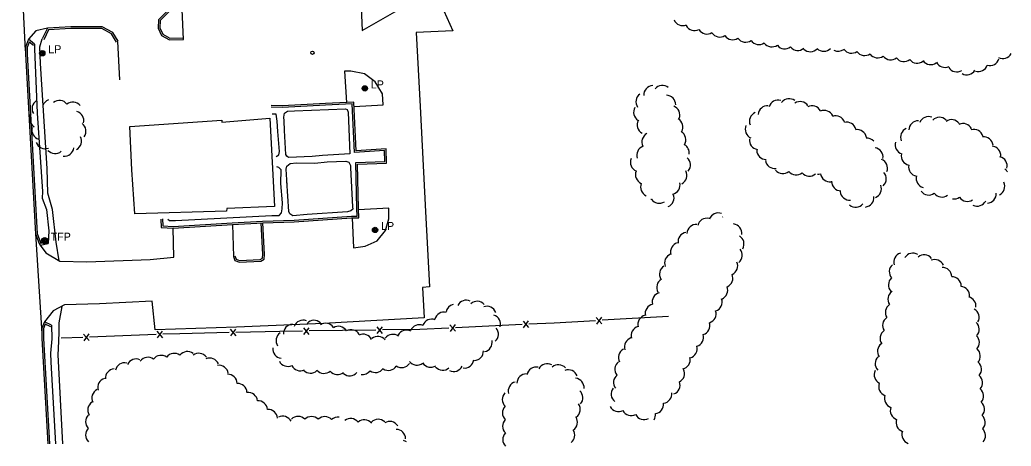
# Model space of a CAD drawing. Extents: x 2402803 to 2427059, y 6985292 to 6997652.
# Drawn here: x 2404119 to 2404714, y 6990684 to 6990940 of the extents above; entities that cross this region are included whole.
import ezdxf

# ---------------------------------------------------------------- set-up
doc = ezdxf.new("R2010")
doc.units = 0
for name, color, linetype in [('p_dtm sidewalk', 7, 'Continuous'), ('p_road - paved curb', 7, 'Continuous'), ('p_structure building', 7, 'Continuous'), ('p_structure fence', 7, 'Continuous'), ('p_structure general', 7, 'Continuous'), ('p_utility manhole', 7, 'Continuous'), ('p_veg woods', 7, 'Continuous')]:
    doc.layers.add(name, color=color, linetype=linetype)

msp = doc.modelspace()

# ---------------------------------------------------------------- linework, layer by layer
at = {"layer": 'p_dtm sidewalk'}
for points in [[(2404142.91, 6990795.04), (2404141.03, 6990806.28), (2404138.82, 6990825.86), (2404136.03, 6990835.62), (2404135.62, 6990850.54), (2404131.7, 6990913.61), (2404131.17, 6990923.49), (2404132.67, 6990928.22)], [(2404128.11, 6990925.14), (2404127.95, 6990922.36), (2404129.66, 6990883.71), (2404132.81, 6990836.75), (2404132.69, 6990832.8), (2404135.24, 6990825.97), (2404136.61, 6990813.18), (2404136.15, 6990805.59)], [(2404277.88, 6990873.33), (2404277.7, 6990879.05), (2404277.52, 6990881.37), (2404278.03, 6990883.76), (2404279.72, 6990884.93), (2404283.95, 6990885.13)], [(2404283.95, 6990885.13), (2404314.46, 6990886.32), (2404315.49, 6990885.96), (2404316.05, 6990884.39), (2404317.1, 6990859.35), (2404300.71, 6990858.22), (2404294.56, 6990857.64), (2404280.35, 6990857.21), (2404279.37, 6990857.89), (2404278.76, 6990859.01), (2404277.88, 6990873.33)], [(2404272.99, 6990857.7), (2404274.63, 6990858.69), (2404274.96, 6990860.63), (2404274.04, 6990872.64), (2404273.57, 6990878.94), (2404273.04, 6990883.09), (2404270.49, 6990883.07)], [(2404279.59, 6990840.44), (2404278.86, 6990850.21), (2404279.42, 6990852), (2404281.33, 6990853.46), (2404285.16, 6990853.89), (2404296.07, 6990853.79), (2404303.47, 6990854.51), (2404314.74, 6990854.84), (2404316.48, 6990854.36), (2404317.58, 6990852.31), (2404317.43, 6990851)], [(2404207.99, 6990820.1), (2404209.04, 6990819.22), (2404212.67, 6990819.25), (2404270.33, 6990822.38), (2404274.78, 6990822.31), (2404276.23, 6990823.96), (2404276.5, 6990826.3), (2404276.71, 6990830), (2404275.83, 6990841.48), (2404275.89, 6990849.63), (2404274.56, 6990851.17), (2404273.4, 6990851.53)], [(2404317.43, 6990851), (2404318.81, 6990827.54), (2404318.87, 6990826.2), (2404317.78, 6990825.14), (2404315.81, 6990824.52), (2404291.64, 6990823.01), (2404282.87, 6990822.17), (2404281.13, 6990823.39), (2404280.59, 6990824.78), (2404279.38, 6990843.21)], [(2404144.42, 6990767.8), (2404142.63, 6990758.01), (2404142.73, 6990751.91), (2404142.18, 6990742.61), (2404141.95, 6990738.66), (2404144.75, 6990685.25)], [(2404138.23, 6990756.48), (2404138.47, 6990748.33), (2404137.68, 6990739.81), (2404137.88, 6990734.32), (2404140.71, 6990685.27)]]:
    msp.add_lwpolyline(points, dxfattribs=at)
at = {"layer": 'p_road - paved curb'}
for points in [[(2404293.41, 6991178.81), (2404288.56, 6991177.04), (2404284.5, 6991172.88), (2404282.54, 6991167.82), (2404284.43, 6991126.82), (2404286.87, 6991077.05), (2404288.44, 6991043.11), (2404288.76, 6991035.23), (2404289.73, 6991010.43), (2404290.42, 6990974.99), (2404289.84, 6990969.34), (2404287.28, 6990963.88), (2404282.1, 6990961), (2404275.36, 6990959.94), (2404251.08, 6990959.64), (2404224.29, 6990958.49), (2404221.09, 6990957.34), (2404218.27, 6990955.63), (2404202.4, 6990939.81), (2404202.23, 6990934.79), (2404204.18, 6990930.34), (2404208.96, 6990927.68), (2404217.39, 6990928.01)], [(2404293.75, 6991177.87), (2404289.12, 6991176.18), (2404285.36, 6991172.33), (2404283.55, 6991167.66), (2404285.43, 6991126.87), (2404287.87, 6991077.1), (2404289.44, 6991043.15), (2404289.76, 6991035.27), (2404290.73, 6991010.46), (2404291.42, 6990974.95), (2404290.82, 6990969.07), (2404288.05, 6990963.16), (2404282.43, 6990960.04), (2404275.44, 6990958.94), (2404251.11, 6990958.64), (2404224.48, 6990957.5), (2404221.52, 6990956.43), (2404218.89, 6990954.84), (2404203.39, 6990939.38), (2404203.24, 6990934.98), (2404204.96, 6990931.05), (2404209.2, 6990928.69), (2404217.35, 6990929.01)], [(2404122.66, 6990921.17), (2404121.06, 6990953.84), (2404119.24, 6990983.48)], [(2404217.39, 6990928.01), (2404216.64, 6990945.87), (2404257.12, 6990947.89), (2404307.04, 6990950.75), (2404323.67, 6990951.86), (2404324.45, 6990933.39), (2404353.98, 6990950.06), (2404368, 6990957.22), (2404378.85, 6990933.11), (2404356.99, 6990932.15), (2404359.23, 6990887.62), (2404362.51, 6990824.66), (2404364.88, 6990779.51), (2404360.76, 6990779.03), (2404361.72, 6990760.99), (2404301.26, 6990757.57), (2404249.25, 6990755.35), (2404200.45, 6990753.66), (2404198.67, 6990771.01), (2404167.1, 6990769.36), (2404146.09, 6990768.63)], [(2404135.87, 6990934.69), (2404128.81, 6990933.05), (2404124.42, 6990928.05)], [(2404178.14, 6990926.88), (2404174.97, 6990932.16), (2404168.57, 6990935.61), (2404149.79, 6990935.56), (2404135.87, 6990934.69), (2404132.67, 6990928.22)], [(2404177.28, 6990926.37), (2404174.25, 6990931.41), (2404168.32, 6990934.61), (2404149.82, 6990934.56), (2404136.51, 6990933.73), (2404133.57, 6990927.78)], [(2404128.11, 6990925.14), (2404124.42, 6990928.05), (2404122.68, 6990923.24), (2404122.64, 6990919.1), (2404128.64, 6990811.29), (2404130.81, 6990805.6), (2404131.45, 6990804.58), (2404136.15, 6990805.59)], [(2404127.49, 6990924.35), (2404124.89, 6990926.41), (2404123.68, 6990923.06), (2404123.64, 6990919.12), (2404129.63, 6990811.5), (2404131.71, 6990806.05), (2404131.92, 6990805.7), (2404135.94, 6990806.57)], [(2404179.29, 6990903.78), (2404178.09, 6990926.77)], [(2404319.7, 6990887.68), (2404337.09, 6990888.79), (2404336.66, 6990895.31), (2404332.31, 6990902.48), (2404325.83, 6990907.24), (2404317.64, 6990908.83), (2404313.98, 6990908.82), (2404315.08, 6990890.16)], [(2404203.76, 6990820.19), (2404204.07, 6990815.06), (2404211.25, 6990814.78), (2404246.69, 6990816.96), (2404264.86, 6990817.97), (2404283.82, 6990818.55), (2404318.16, 6990820.88), (2404322.56, 6990820.99), (2404322.33, 6990826.31), (2404321.69, 6990853.07), (2404339.08, 6990853.79), (2404338.85, 6990862.38), (2404320.84, 6990861.18), (2404319.58, 6990890.38), (2404302.48, 6990889.55), (2404276.67, 6990888.03), (2404269.93, 6990888.34)], [(2404204.76, 6990820.25), (2404205.01, 6990816.02), (2404211.24, 6990815.78), (2404246.63, 6990817.96), (2404264.82, 6990818.97), (2404283.77, 6990819.55), (2404318.11, 6990821.88), (2404321.52, 6990821.96), (2404321.33, 6990826.28), (2404320.67, 6990854.03), (2404338.05, 6990854.75), (2404337.88, 6990861.31), (2404319.89, 6990860.11), (2404318.62, 6990889.33), (2404302.53, 6990888.55), (2404276.68, 6990887.03), (2404269.88, 6990887.34)], [(2404318.57, 6990820.89), (2404319.41, 6990802.82), (2404326.34, 6990803.82), (2404333.6, 6990807.05), (2404338.52, 6990813.24), (2404340.59, 6990820.36), (2404340.45, 6990826.77), (2404322.35, 6990825.76)], [(2404131.45, 6990804.58), (2404134.81, 6990799.95), (2404143.21, 6990794.86), (2404159.5, 6990794.58), (2404197.44, 6990795.94), (2404211.65, 6990797.34), (2404211.25, 6990814.78)], [(2404246.69, 6990816.96), (2404247.32, 6990797.71)], [(2404247.32, 6990797.71), (2404248.26, 6990795.26), (2404250.89, 6990794.26), (2404263.66, 6990794.86), (2404265.77, 6990796.11), (2404265.88, 6990798.94), (2404264.86, 6990817.97)], [(2404248.25, 6990798.07), (2404249.03, 6990796.04), (2404251.05, 6990795.27), (2404263.36, 6990795.85), (2404264.79, 6990796.69), (2404264.88, 6990798.93), (2404263.86, 6990817.92)], [(2404128.64, 6990811.29), (2404132.39, 6990751.55)], [(2404146.09, 6990768.63), (2404139.23, 6990765.21), (2404133.95, 6990758.47)], [(2404138.23, 6990756.48), (2404133.95, 6990758.47), (2404132.38, 6990754.64), (2404132.41, 6990748.47), (2404136.01, 6990685.22)], [(2404137.81, 6990755.57), (2404134.48, 6990757.12), (2404133.38, 6990754.45), (2404133.41, 6990748.5), (2404137.01, 6990685.28)]]:
    msp.add_lwpolyline(points, dxfattribs=at)
at = {"layer": 'p_structure building'}
msp.add_lwpolyline([(2404271.94, 6990827.78), (2404243.31, 6990826.57), (2404243.14, 6990824.94), (2404188.24, 6990823.3), (2404186.36, 6990849.78), (2404185.28, 6990875.67), (2404240.3, 6990879.47), (2404240.28, 6990878.29), (2404269.17, 6990880.76)], close=True, dxfattribs=at)
at = {"layer": 'p_structure fence'}
for p, q in [((2404464.85, 6990761.2), (2404468.28, 6990757.39)), ((2404468.05, 6990761.38), (2404465.08, 6990757.2)), ((2404508.28, 6990761.7), (2404468.36, 6990759.42)), ((2404245.39, 6990754.08), (2404248.68, 6990750.16)), ((2404248.59, 6990754.16), (2404245.48, 6990750.08)), ((2404289.33, 6990754.96), (2404292.58, 6990751.01)), ((2404292.53, 6990755.01), (2404289.38, 6990750.96)), ((2404332.67, 6990753.58), (2404292.76, 6990753.04)), ((2404333.24, 6990755.56), (2404336.49, 6990751.6)), ((2404336.44, 6990755.6), (2404333.29, 6990751.56)), ((2404377.08, 6990756.77), (2404380.46, 6990752.93)), ((2404380.27, 6990756.93), (2404377.27, 6990752.78)), ((2404420.47, 6990756.87), (2404380.57, 6990754.97)), ((2404420.97, 6990758.87), (2404424.35, 6990755.02)), ((2404424.16, 6990759.02), (2404421.16, 6990754.87)), ((2404156.96, 6990749.21), (2404143.99, 6990748.72)), ((2404157.48, 6990751.2), (2404160.83, 6990747.32)), ((2404160.68, 6990751.32), (2404157.64, 6990747.2)), ((2404200.91, 6990750.87), (2404160.96, 6990749.36)), ((2404201.43, 6990752.86), (2404204.78, 6990748.99)), ((2404204.63, 6990752.98), (2404201.58, 6990748.86))]:
    msp.add_line(p, q, dxfattribs=at)
for points in [[(2404376.58, 6990754.78), (2404359.04, 6990753.94), (2404336.66, 6990753.64)], [(2404464.37, 6990759.2), (2404439.72, 6990757.79), (2404424.46, 6990757.06)], [(2404244.84, 6990752.1), (2404215.19, 6990751.41), (2404204.9, 6990751.02)], [(2404288.76, 6990752.99), (2404275.1, 6990752.8), (2404248.84, 6990752.19)]]:
    msp.add_lwpolyline(points, dxfattribs=at)
at = {"layer": 'p_structure general'}
msp.add_circle((2404294.67, 6990920.01), 1, dxfattribs=at)
at = {"layer": 'p_utility manhole'}
for centre, radius in [((2404132.73, 6990919.69), 1.6), ((2404132.73, 6990919.69), 1.3), ((2404132.73, 6990919.69), 1), ((2404132.73, 6990919.69), 0.539), ((2404132.73, 6990919.69), 0.192), ((2404326.13, 6990898.56), 1.6), ((2404326.13, 6990898.56), 1.3), ((2404326.13, 6990898.56), 1), ((2404326.13, 6990898.56), 0.539), ((2404326.13, 6990898.56), 0.192), ((2404332.28, 6990813.62), 1.6), ((2404332.28, 6990813.62), 1.3), ((2404332.28, 6990813.62), 1), ((2404332.28, 6990813.62), 0.539), ((2404332.28, 6990813.62), 0.192), ((2404134.14, 6990807.19), 1.9), ((2404134.14, 6990807.19), 1.44), ((2404134.14, 6990807.19), 0.973), ((2404134.14, 6990807.19), 0.539), ((2404134.14, 6990807.19), 0.192)]:
    msp.add_circle(centre, radius, dxfattribs=at)
at = {"layer": 'p_veg woods'}
for centre, start, end in [((2404516.76, 6990941.89), 202.66105, 292.66105), ((2404523.82, 6990938.97), 207.75609, 297.75609), ((2404531.23, 6990936.85), 211.8676, 301.8676), ((2404538.93, 6990935.06), 213.24511, 303.24511), ((2404546.68, 6990933.42), 214.35125, 304.35125), ((2404554.53, 6990931.95), 214.61226, 304.61226), ((2404562.38, 6990930.52), 214.94625, 304.94625), ((2404570.18, 6990929.13), 216.00257, 306.00257), ((2404577.93, 6990927.93), 218.20101, 308.20101), ((2404585.8, 6990927.02), 219.41218, 309.41218), ((2404593.25, 6990926.24), 226.81252, 316.81252), ((2404601.32, 6990926.54), 225.69946, 315.69946), ((2404609.96, 6990926.53), 243.37683, 306.73273), ((2404617.98, 6990925.35), 215.1462, 305.1462), ((2404625.89, 6990923.95), 214.75018, 304.75018), ((2404633.66, 6990922.52), 216.12763, 306.12763), ((2404641.46, 6990921.32), 217.68033, 307.68033), ((2404649.36, 6990920.32), 218.16224, 308.16224), ((2404657.31, 6990919.36), 218.14193, 308.14193), ((2404665.46, 6990918.5), 215.35029, 305.35029), ((2404673.96, 6990916.84), 205.90598, 295.90598), ((2404701, 6990917.98), 252.72481, 342.72481), ((2404708.71, 6990922.17), 242.04325, 332.04325), ((2404681.08, 6990914.15), 211.78403, 301.78403), ((2404687.09, 6990912.36), 239.567, 329.567), ((2404693.92, 6990914.26), 252.72481, 342.72481), ((2404499.02, 6990894.58), 92.7016, 182.7016), ((2404504.55, 6990894.73), 51.25117, 141.25117), ((2404132.21, 6990886.44), 121.59958, 211.59958), ((2404138.41, 6990886.39), 111.16312, 159.19227), ((2404142.97, 6990885.72), 38.03564, 128.03564), ((2404150.91, 6990884.75), 38.03564, 128.03564), ((2404494.31, 6990890.62), 125.70134, 215.70134), ((2404506.88, 6990888.81), 359.35934, 89.35934), ((2404574.03, 6990885.93), 74.35115, 164.35115), ((2404580.52, 6990886.75), 52.45348, 142.45348), ((2404587.09, 6990885.05), 33.24755, 123.24755), ((2404151.94, 6990879.33), 344.51694, 74.51694), ((2404492.95, 6990884.25), 149.04069, 239.04069), ((2404509.38, 6990882.61), 339.12815, 69.12815), ((2404567.64, 6990882.55), 86.06118, 176.06118), ((2404594.24, 6990882.52), 27.02156, 117.02156), ((2404601.51, 6990879.74), 23.88066, 113.88066), ((2404130.67, 6990880.45), 149.71075, 239.71075), ((2404495.12, 6990876.7), 151.11677, 241.11677), ((2404511.19, 6990875.44), 329.93628, 59.93628), ((2404562.38, 6990878.88), 113.15778, 203.15778), ((2404608.48, 6990876.48), 19.56683, 109.56683), ((2404657.94, 6990873.46), 88.0937, 178.0937), ((2404664.12, 6990876), 68.13528, 158.13528), ((2404670.71, 6990875.57), 45.32214, 135.32214), ((2404677.91, 6990874.2), 35.35456, 125.35456), ((2404132.12, 6990873.53), 164.39576, 254.39576), ((2404153.24, 6990872.9), 324.01076, 54.01076), ((2404512.95, 6990867.76), 328.24323, 58.24323), ((2404559.86, 6990874.03), 156.25217, 246.25217), ((2404615.18, 6990872.65), 15.33536, 105.33536), ((2404621.36, 6990868.19), 9.76243, 99.76243), ((2404653, 6990869.32), 113.14666, 203.14666), ((2404684.9, 6990871.84), 26.16688, 116.16688), ((2404691.35, 6990868.34), 16.52494, 106.52494), ((2404150.6, 6990867.03), 296.97457, 26.97457), ((2404497.91, 6990866.52), 117.83577, 207.83577), ((2404562.38, 6990867.53), 171.60004, 261.60004), ((2404627.02, 6990863.17), 40.70404, 93.55488), ((2404697.21, 6990863.82), 7.57906, 97.57906), ((2404134.38, 6990868.04), 200.49716, 290.49716), ((2404140.39, 6990865.1), 220.74048, 310.74048), ((2404146.04, 6990863.58), 262.52168, 352.52168), ((2404494.83, 6990858.5), 108.94659, 198.94659), ((2404515, 6990859.94), 351.80112, 59.45158), ((2404566.77, 6990861.56), 180.28299, 270.28299), ((2404631.23, 6990857.34), 351.43085, 81.43085), ((2404649.76, 6990864.83), 163.87643, 253.87643), ((2404701.81, 6990858.31), 355.3713, 85.3713), ((2404491.05, 6990854.23), 157.23182, 247.23182), ((2404515.72, 6990852.64), 319.86811, 49.86811), ((2404571.9, 6990856.15), 188.62086, 278.62086), ((2404633.89, 6990850.73), 338.13629, 68.13629), ((2404653.46, 6990858.09), 168.28272, 258.28272), ((2404705.69, 6990851.98), 346.97861, 76.97861), ((2404494.07, 6990846.82), 157.23182, 247.23182), ((2404513.67, 6990846.41), 297.86651, 27.86651), ((2404576.77, 6990853.05), 219.79264, 309.79264), ((2404584.73, 6990852.32), 219.79264, 309.79264), ((2404657.8, 6990851.52), 170.14158, 260.14158), ((2404706.61, 6990845.58), 30.37966, 53.64876), ((2404592.7, 6990851.6), 219.79264, 309.79264), ((2404598.35, 6990852.8), 262.04808, 279.04146), ((2404604.95, 6990848.12), 187.63706, 277.63706), ((2404611.66, 6990842.78), 179.37674, 269.37674), ((2404633.16, 6990844.35), 312.5332, 42.5332), ((2404662.44, 6990844.48), 163.85334, 253.85334), ((2404497.1, 6990839.42), 157.23182, 247.23182), ((2404509.54, 6990840.67), 282.87035, 12.87035), ((2404630.21, 6990838.34), 291.77287, 21.77287), ((2404664.25, 6990840.23), 216.43428, 306.43428), ((2404704.17, 6990839.78), 295.9708, 25.9708), ((2404494.82, 6990836.88), 298.70357, 303.50244), ((2404502.65, 6990835.28), 213.50244, 303.50244), ((2404505.87, 6990832.85), 292.31074, 22.31074), ((2404616.86, 6990837.18), 184.72216, 274.72216), ((2404625.7, 6990833.01), 276.21473, 6.21473), ((2404672.16, 6990839.04), 216.43428, 306.43428), ((2404679.48, 6990837.89), 259.78718, 304.40739), ((2404687.34, 6990836.42), 214.40739, 304.40739), ((2404693.39, 6990833.6), 242.70833, 332.70833), ((2404699.14, 6990835.37), 273.22572, 3.22572), ((2404620.44, 6990832.99), 230.51551, 320.51551), ((2404531.23, 6990815.04), 76.54601, 166.54601), ((2404538.04, 6990818.21), 69.47021, 159.47021), ((2404543.99, 6990816.74), 124.02934, 127.25453), ((2404524.95, 6990811.29), 86.73266, 176.73266), ((2404546.56, 6990811.63), 353.0443, 83.0443), ((2404519.57, 6990806.56), 99.08163, 189.08163), ((2404547.83, 6990805.22), 329.51744, 59.51744), ((2404515.12, 6990800.53), 106.57091, 196.57091), ((2404546.85, 6990798.55), 309.57102, 39.57102), ((2404511.49, 6990793.78), 111.44378, 201.44378), ((2404648.95, 6990794.35), 107.51333, 197.51333), ((2404654.74, 6990794.06), 58.13563, 148.13563), ((2404661.47, 6990793.03), 39.31062, 129.31062), ((2404667.82, 6990790.27), 22.81508, 112.81508), ((2404508.46, 6990787.19), 122.58424, 212.58424), ((2404544.08, 6990792.12), 293.96964, 23.96964), ((2404646.27, 6990788.52), 130.51176, 220.51176), ((2404672.44, 6990785.48), 1.70038, 91.70038), ((2404506.79, 6990779.16), 119.79596, 209.79596), ((2404541.16, 6990784.72), 293.42845, 23.42845), ((2404645.75, 6990780.68), 132.55598, 222.55598), ((2404678.1, 6990779.96), 0.36266, 90.36266), ((2404538.07, 6990777.45), 291.94612, 21.94612), ((2404683.1, 6990774.17), 355.34127, 85.34127), ((2404386.87, 6990765.84), 63.93675, 153.93675), ((2404504.1, 6990770.51), 104.65274, 194.65274), ((2404534.72, 6990770.37), 289.55625, 19.55625), ((2404645.44, 6990772.08), 124.06512, 214.06512), ((2404686.94, 6990767.9), 353.08747, 75.89), ((2404380.37, 6990763.36), 102.70637, 168.99511), ((2404393.44, 6990765.18), 41.86917, 131.86917), ((2404399.32, 6990762.21), 19.91548, 109.91548), ((2404499.86, 6990763.48), 101.65602, 191.65602), ((2404643.9, 6990764.15), 123.04818, 213.04818), ((2404688.85, 6990761.18), 330.84044, 60.84044), ((2404289.1, 6990753.84), 69.66941, 159.66941), ((2404366.27, 6990754.49), 69.42003, 159.42003), ((2404373.63, 6990758.71), 76.33679, 166.33679), ((2404401.83, 6990757.16), 342.98177, 72.98177), ((2404495.5, 6990756.95), 103.71028, 193.71028), ((2404531.09, 6990763.38), 287.73897, 17.73897), ((2404642.25, 6990756.35), 123.38689, 213.38689), ((2404283.03, 6990751.51), 93.85465, 183.85465), ((2404295.71, 6990753.78), 47.55142, 137.55142), ((2404302.64, 6990752), 34.11143, 124.11143), ((2404310.26, 6990750.18), 31.71105, 121.71105), ((2404317.88, 6990748.15), 30.07664, 120.07664), ((2404351.13, 6990747.98), 62.45916, 152.45916), ((2404358.84, 6990751.09), 66.92011, 156.92011), ((2404400.58, 6990751.16), 310.20933, 40.20933), ((2404491.41, 6990750.18), 105.00898, 195.00898), ((2404527.4, 6990756.3), 287.54173, 17.54173), ((2404688.88, 6990754.03), 317.72112, 47.72112), ((2404278.51, 6990747.25), 124.33675, 214.33675), ((2404325.09, 6990745.47), 25.50803, 115.50803), ((2404333.9, 6990744.12), 38.61499, 128.61499), ((2404342.86, 6990745.34), 52.99153, 142.99153), ((2404487.46, 6990743.45), 107.8349, 197.8349), ((2404523.65, 6990749.3), 286.71946, 16.71946), ((2404640.75, 6990748.53), 123.94908, 213.94908), ((2404689.01, 6990746.13), 316.29488, 46.29488), ((2404276.51, 6990742.24), 173.45449, 263.45449), ((2404396.84, 6990746.18), 281.39093, 11.39093), ((2404483.82, 6990736.99), 116.70291, 206.70291), ((2404519.79, 6990742.39), 285.42416, 15.42416), ((2404639.15, 6990740.8), 125.52601, 215.52601), ((2404689.54, 6990737.96), 319.00879, 49.00879), ((2404188.93, 6990730.58), 65.70692, 155.70692), ((2404196.01, 6990731.59), 53.26091, 143.26091), ((2404203.95, 6990732.77), 53.57971, 143.57971), ((2404211.86, 6990733.97), 53.59463, 143.59463), ((2404219.68, 6990735.03), 52.05666, 142.05666), ((2404226.59, 6990733.98), 36.90078, 126.90078), ((2404233.1, 6990731.13), 23.28869, 113.28869), ((2404385.8, 6990736.44), 262.66939, 352.66939), ((2404391.59, 6990740.94), 272.38211, 2.38211), ((2404515.57, 6990735.79), 282.97415, 12.97415), ((2404637.8, 6990733.46), 133.42922, 223.42922), ((2404176.21, 6990724.69), 94.43716, 184.43716), ((2404182.06, 6990728.27), 77.14283, 167.14283), ((2404238.66, 6990726.78), 8.77778, 98.77778), ((2404279.95, 6990737.43), 205.56305, 295.56305), ((2404287.47, 6990734.77), 205.56305, 295.56305), ((2404332.54, 6990733.76), 234.57334, 324.57334), ((2404340.29, 6990735.05), 236.5962, 326.5962), ((2404348.21, 6990736.72), 235.24552, 325.24552), ((2404357.4, 6990738.2), 217.12296, 307.12296), ((2404365.62, 6990736.92), 212.65688, 302.65688), ((2404372.82, 6990735.14), 221.34037, 311.34037), ((2404379.36, 6990734.33), 243.96334, 333.96334), ((2404428.9, 6990725.75), 78.26477, 168.26477), ((2404435.53, 6990727.74), 62.03863, 152.03863), ((2404442.14, 6990727.13), 41.09196, 131.09196), ((2404448.14, 6990724.08), 21.06586, 111.06586), ((2404481.73, 6990730.15), 128.90153, 218.90153), ((2404512.2, 6990727.53), 296.64697, 26.64697), ((2404690.24, 6990729.95), 319.66183, 49.66183), ((2404171.63, 6990719.2), 106.82122, 196.82122), ((2404243.96, 6990721.4), 1.893, 91.893), ((2404285.51, 6990733.56), 311.83796, 313.46016), ((2404293.51, 6990733.35), 223.46016, 313.46016), ((2404301.66, 6990733.25), 221.29316, 311.29316), ((2404309.72, 6990732.46), 219.87228, 309.87228), ((2404317.02, 6990731.78), 229.60063, 319.60063), ((2404324.65, 6990732.43), 262.09983, 324.57334), ((2404422.95, 6990721.58), 88.71976, 178.71976), ((2404451.93, 6990719.05), 354.16136, 84.16136), ((2404480.87, 6990722.07), 127.17875, 217.17875), ((2404637.21, 6990726.76), 153.91319, 243.91319), ((2404690.88, 6990721.98), 319.60379, 49.60379), ((2404168.04, 6990712.78), 116.46082, 206.46082), ((2404249.8, 6990715.94), 1.88959, 91.88959), ((2404417.73, 6990716.92), 104.23911, 194.23911), ((2404479.51, 6990715.1), 141.28761, 231.28761), ((2404509.51, 6990720.56), 289.4106, 19.4106), ((2404639.89, 6990719.74), 160.75031, 250.75031), ((2404691.47, 6990714.02), 319.26268, 49.26268), ((2404256.09, 6990710.58), 5.73099, 95.73099), ((2404414.21, 6990711.94), 135.60653, 225.60653), ((2404451.22, 6990712.99), 318.20277, 48.20277), ((2404504.55, 6990715.3), 277.0306, 7.0306), ((2404643.37, 6990712.53), 160.75031, 250.75031), ((2404165.62, 6990705.58), 122.42952, 212.42952), ((2404262.14, 6990705.47), 4.52277, 94.52277), ((2404414.3, 6990703.94), 135.60653, 225.60653), ((2404449.67, 6990706.01), 305.05992, 35.05992), ((2404478.3, 6990710.26), 207.49076, 297.49076), ((2404499.65, 6990709.03), 277.0306, 7.0306), ((2404646.84, 6990705.33), 160.75031, 250.75031), ((2404692.04, 6990706.05), 319.17081, 49.17081), ((2404164.29, 6990698.6), 135.20968, 225.20968), ((2404268.21, 6990700.27), 4.40789, 94.40789), ((2404276.83, 6990696.27), 26.90072, 116.90072), ((2404286.09, 6990696.13), 44.10624, 134.10624), ((2404294.14, 6990696.06), 44.80078, 134.80078), ((2404302.11, 6990696), 44.34095, 134.34095), ((2404309.98, 6990695.71), 82.00368, 132.56695), ((2404317.67, 6990694.83), 38.84636, 128.84636), ((2404334.17, 6990694.38), 46.36627, 136.36627), ((2404447.99, 6990698.27), 303.84726, 33.84726), ((2404485.93, 6990707.85), 207.49076, 297.49076), ((2404493.56, 6990705.45), 207.49076, 297.49076), ((2404494.76, 6990702.76), 327.95327, 7.0306), ((2404692.48, 6990698.14), 318.07209, 48.07209), ((2404164.32, 6990690.6), 135.20968, 225.20968), ((2404325.7, 6990694.06), 39.73872, 129.73872), ((2404341.05, 6990693.11), 32.13096, 122.13096), ((2404414.38, 6990695.94), 135.60653, 225.60653), ((2404650.32, 6990698.13), 160.75031, 250.75031), ((2404692.62, 6990690.26), 318.05135, 46.32728), ((2404344.92, 6990688.36), 0.02936, 90.02936), ((2404414.47, 6990687.94), 135.60653, 225.60653), ((2404446.32, 6990690.55), 307.96188, 32.38751), ((2404653.79, 6990690.92), 160.75031, 250.75031), ((2404347.77, 6990681.89), 53.42895, 74.56036)]:
    msp.add_arc(centre, 5.65, start, end, dxfattribs=at)

# ---------------------------------------------------------------- texts
at = {"layer": 'p_utility manhole'}
for s, p in [('  LP', (2404132.73, 6990919.69)), ('  LP', (2404326.13, 6990898.56)), ('  LP', (2404332.28, 6990813.62)), ('  TFP', (2404134.14, 6990807.19))]:
    msp.add_text(s, height=4.8, dxfattribs=at).set_placement(p)

doc.saveas('drawing.dxf')
